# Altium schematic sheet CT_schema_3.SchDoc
size 522 x 390 mm
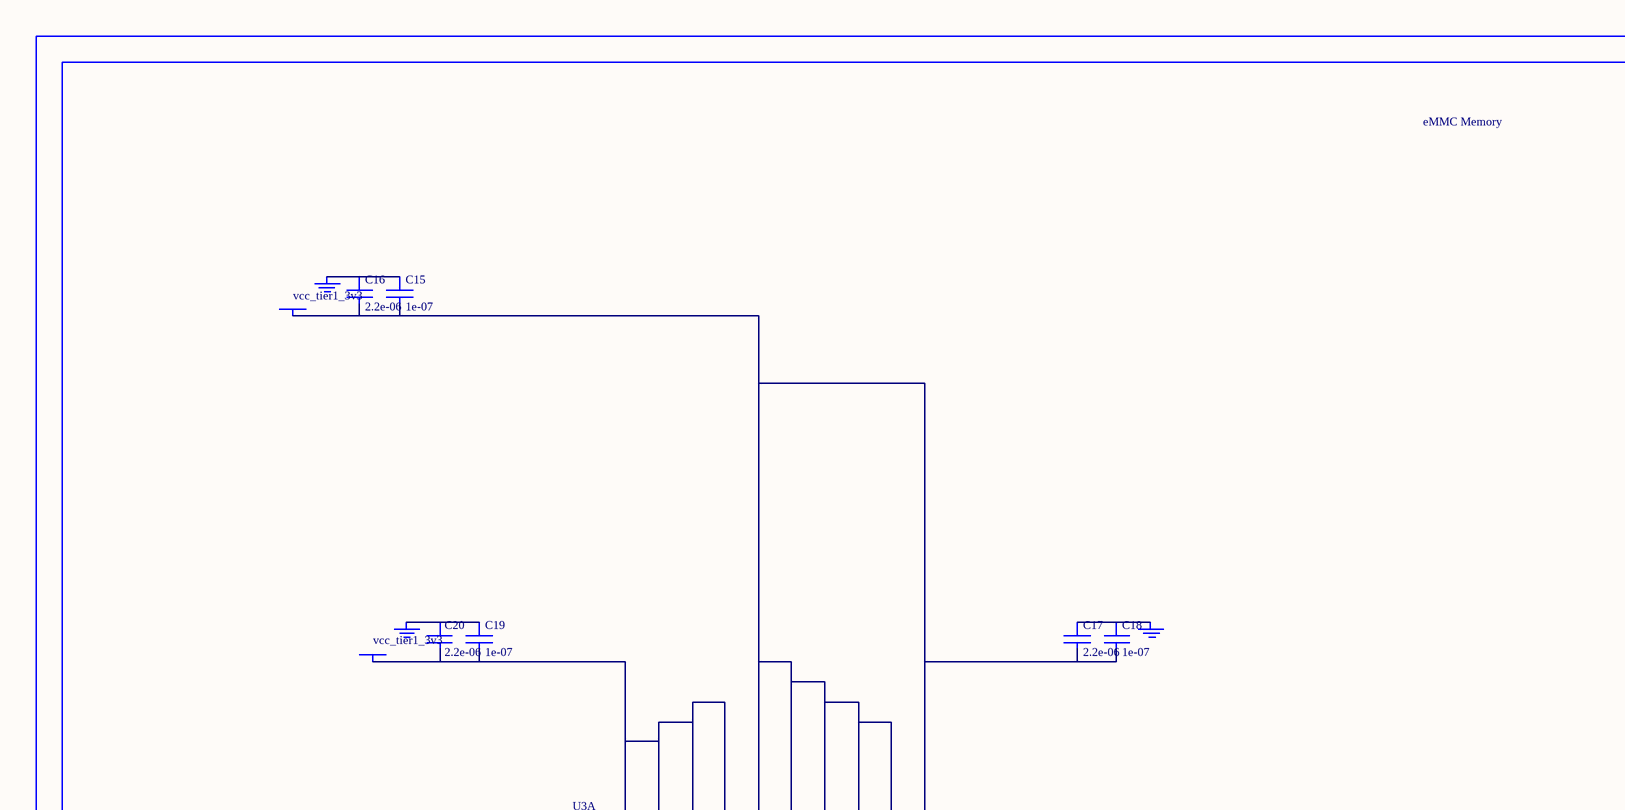
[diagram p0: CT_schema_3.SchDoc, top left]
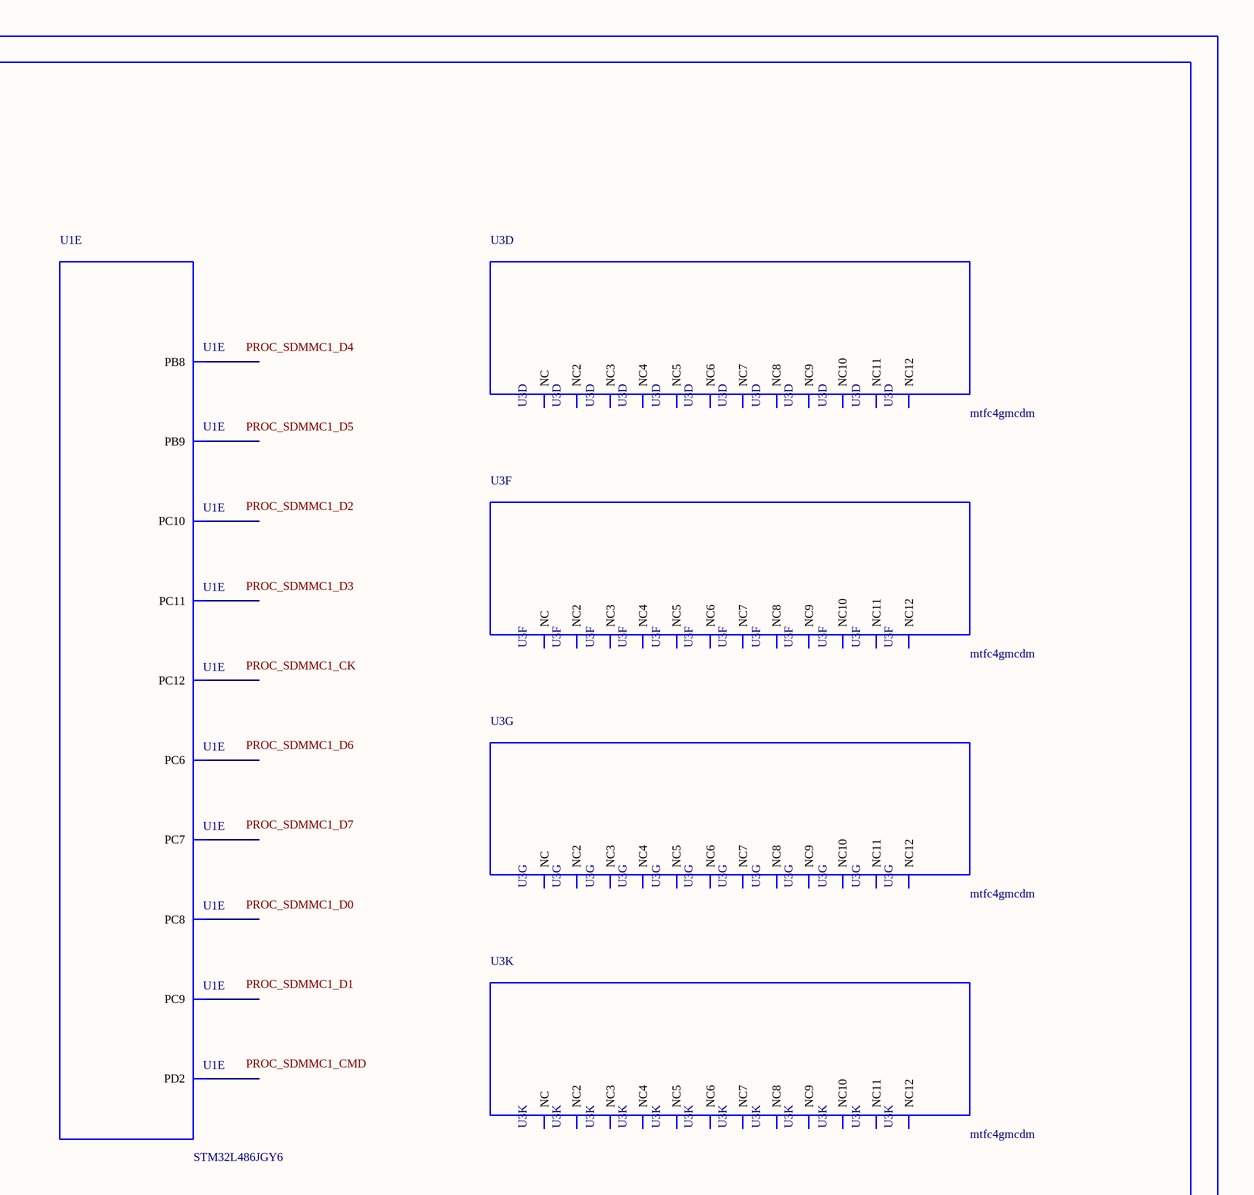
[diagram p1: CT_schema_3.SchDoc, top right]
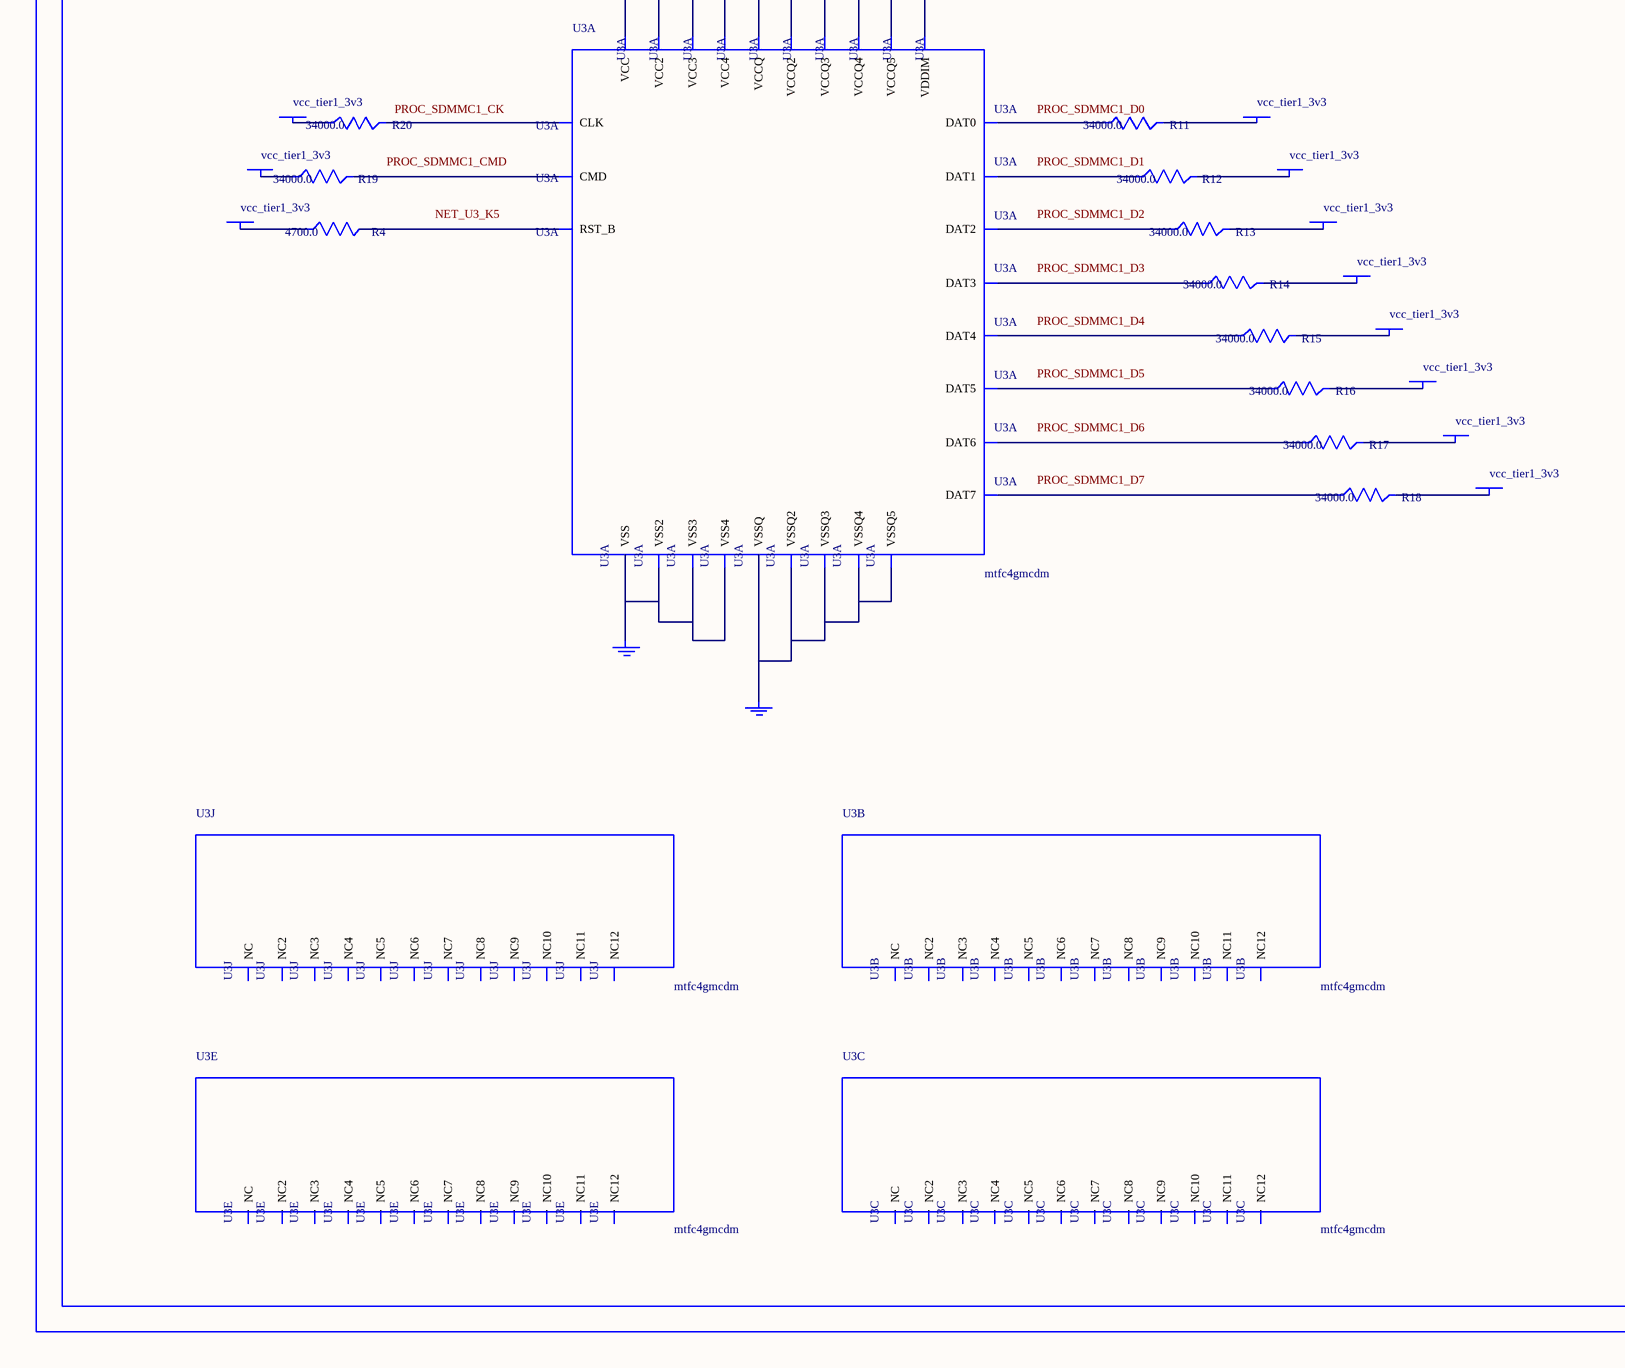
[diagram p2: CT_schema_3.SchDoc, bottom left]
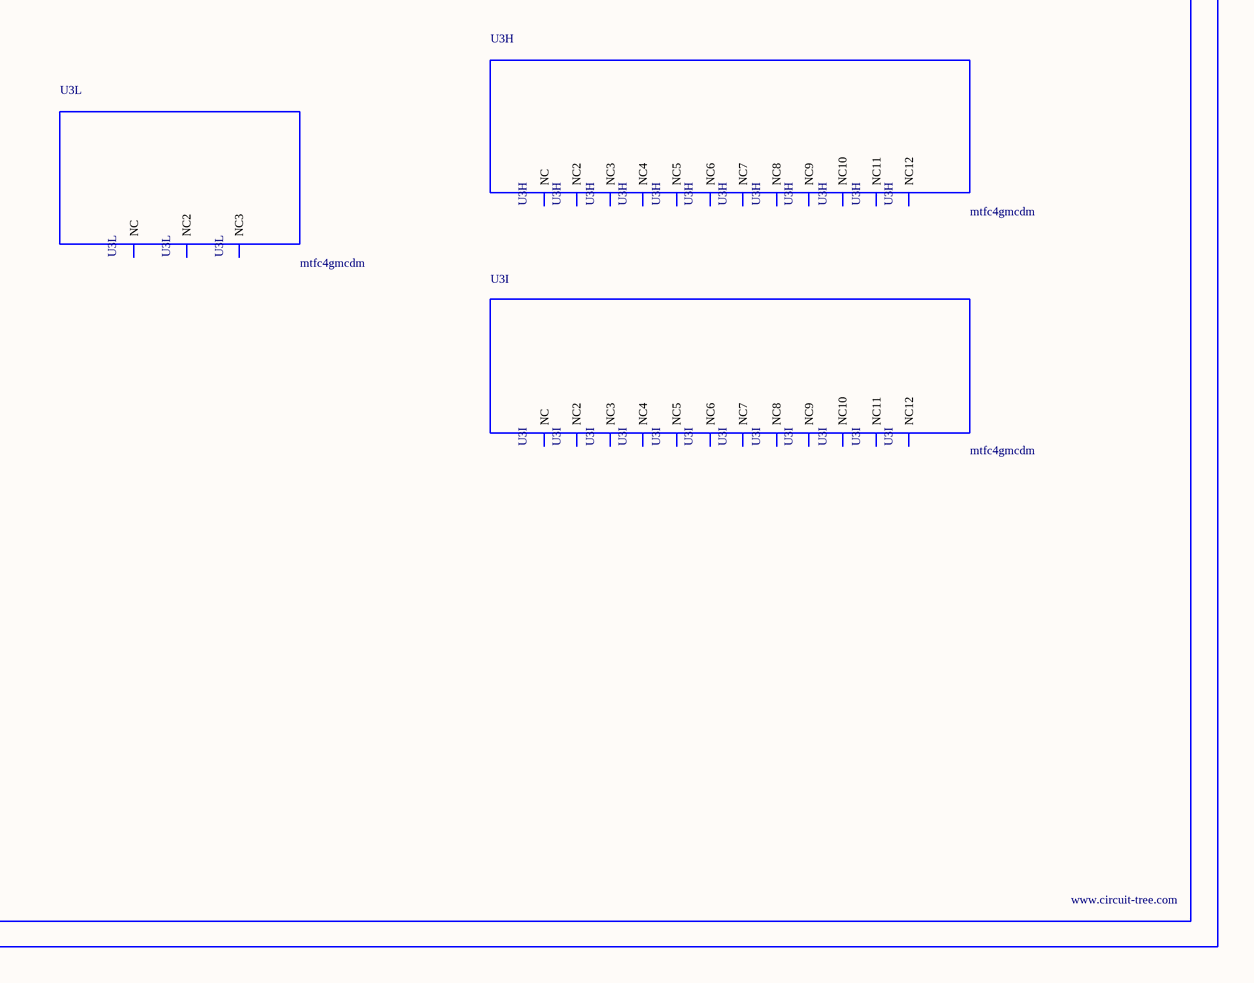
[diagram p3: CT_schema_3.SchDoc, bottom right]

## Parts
BORDER2  (no value)
C15  1e-07  [C0402]
C16  2.2e-06  [C0603]
C17  2.2e-06  [C0603]
C18  1e-07  [C0402]
C19  1e-07  [C0402]
C20  2.2e-06  [C0603]
GND_INSTANCE_2_0  (no value)
GND_INSTANCE_2_1  (no value)
GND_INSTANCE_2_2  (no value)
GND_INSTANCE_2_3  (no value)
GND_INSTANCE_2_4  (no value)
POWER_INSTANCE_2_0  vcc_tier1_3v3
POWER_INSTANCE_2_1  vcc_tier1_3v3
POWER_INSTANCE_2_2  vcc_tier1_3v3
POWER_INSTANCE_2_3  vcc_tier1_3v3
POWER_INSTANCE_2_4  vcc_tier1_3v3
POWER_INSTANCE_2_5  vcc_tier1_3v3
POWER_INSTANCE_2_6  vcc_tier1_3v3
POWER_INSTANCE_2_7  vcc_tier1_3v3
POWER_INSTANCE_2_8  vcc_tier1_3v3
POWER_INSTANCE_2_9  vcc_tier1_3v3
POWER_INSTANCE_2_10  vcc_tier1_3v3
POWER_INSTANCE_2_11  vcc_tier1_3v3
POWER_INSTANCE_2_12  vcc_tier1_3v3
R4  4700.0  [R0603]
R11  34000.0  [R0603]
R12  34000.0  [R0603]
R13  34000.0  [R0603]
R14  34000.0  [R0603]
R15  34000.0  [R0603]
R16  34000.0  [R0603]
R17  34000.0  [R0603]
R18  34000.0  [R0603]
R19  34000.0  [R0603]
R20  34000.0  [R0603]
U1  STM32L486JGY6  [WLCSP72]  (part E of 7)
U3  mtfc4gmcdm  [TFBGA-153]  (parts A,B,C,D,E,F,G,H,I,J,K,L of 12)

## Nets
NetC15_1: C15.1 C16.1 GND_INSTANCE_2_0.0(GND)
NetC15_2: C15.2 C16.2 C17.2 C18.2 POWER_INSTANCE_2_0.0(PWR) U3.C2(VDDIM) U3.C6(VCCQ) U3.M4(VCCQ2) U3.N4(VCCQ3) U3.P3(VCCQ4) U3.P5(VCCQ5)
NetC17_1: C17.1 C18.1 GND_INSTANCE_2_1.0(GND)
NetC19_1: C19.1 C20.1 GND_INSTANCE_2_2.0(GND)
NetC19_2: C19.2 C20.2 POWER_INSTANCE_2_1.0(PWR) U3.E6(VCC) U3.F5(VCC2) U3.J10(VCC3) U3.K9(VCC4)
NetGND_INSTANCE_2_3_0: GND_INSTANCE_2_3.0(GND) U3.E7(VSS) U3.G5(VSS2) U3.H10(VSS3) U3.K8(VSS4)
NetGND_INSTANCE_2_4_0: GND_INSTANCE_2_4.0(GND) U3.C4(VSSQ) U3.N2(VSSQ2) U3.N5(VSSQ3) U3.P4(VSSQ4) U3.P6(VSSQ5)
NetPOWER_INSTANCE_2_2_0: POWER_INSTANCE_2_2.0(PWR) R11.2
NetPOWER_INSTANCE_2_3_0: POWER_INSTANCE_2_3.0(PWR) R12.2
NetPOWER_INSTANCE_2_4_0: POWER_INSTANCE_2_4.0(PWR) R13.2
NetPOWER_INSTANCE_2_5_0: POWER_INSTANCE_2_5.0(PWR) R14.2
NetPOWER_INSTANCE_2_6_0: POWER_INSTANCE_2_6.0(PWR) R15.2
NetPOWER_INSTANCE_2_7_0: POWER_INSTANCE_2_7.0(PWR) R16.2
NetPOWER_INSTANCE_2_8_0: POWER_INSTANCE_2_8.0(PWR) R17.2
NetPOWER_INSTANCE_2_9_0: POWER_INSTANCE_2_9.0(PWR) R18.2
NetPOWER_INSTANCE_2_10_0: POWER_INSTANCE_2_10.0(PWR) R19.1
NetPOWER_INSTANCE_2_11_0: POWER_INSTANCE_2_11.0(PWR) R20.1
NetPOWER_INSTANCE_2_12_0: POWER_INSTANCE_2_12.0(PWR) R4.1
NetR4_2: R4.2 U3.K5(RST_B)
NetR11_1: R11.1 U3.A3(DAT0)
NetR12_1: R12.1 U3.A4(DAT1)
NetR13_1: R13.1 U3.A5(DAT2)
NetR14_1: R14.1 U3.B2(DAT3)
NetR15_1: R15.1 U3.B3(DAT4)
NetR16_1: R16.1 U3.B4(DAT5)
NetR17_1: R17.1 U3.B5(DAT6)
NetR18_1: R18.1 U3.B6(DAT7)
NetR19_2: R19.2 U3.M5(CMD)
NetR20_2: R20.2 U3.M6(CLK)

Not connected (* = marked no-connect by the designer): U1 A3(PD2) B3(PC12) C3(PC11) D3(PC10) E1(PC9) E7(PB8) E8(PB9) F1(PC7) F2(PC8) F3(PC6); U3 A1(NC) A2(NC7) A6(NC8) A7(NC9) A8(NC10) A9(NC11) A10(NC2) A11(NC3) A12(NC4) A13(NC5) A14(NC6) B1(NC12) B7(NC6) B8(NC7) B9(NC8) B10(NC) B11(NC2) B12(NC3) B13(NC4) B14(NC5) C1(NC9) C3(NC10) C5(NC11) C7(NC12) C8(NC6) C9(NC7) C10(NC) C11(NC2) C12(NC3) C13(NC4) C14(NC5) D1(NC8) D2(NC10) D3(NC11) D4(NC12) D12(NC9) D13(NC) D14(NC2) E1(NC3) E2(NC8) E3(NC9) E5(NC10) E8(NC11) E9(NC12) E10(NC4) E12(NC5) E13(NC6) E14(NC7) F1(NC) F2(NC6) F3(NC7) F10(NC2) F12(NC3) F13(NC4) F14(NC5) G1(NC8) G2(NC11) G3(NC12) G10(NC9) G12(NC10) G13(NC) G14(NC2) H1(NC3) H2(NC7) H3(NC8) H5(NC9) H12(NC4) H13(NC5) H14(NC6) J1(NC10) J2(NC11) J3(NC12) J5(NC4) J12(NC) J13(NC2) J14(NC3) K1(NC5) K2(NC9) K3(NC10) K6(NC11) K7(NC12) K10(NC6) K12(NC7) K13(NC8) K14(NC) L1(NC2) L2(NC6) L3(NC7) L12(NC3) L13(NC4) L14(NC5) M1(NC8) M2(NC9) M3(NC10) M7(NC11) M8(NC12) M9(NC6) M10(NC) M11(NC2) M12(NC3) M13(NC4) M14(NC5) N1(NC7) N3(NC8) N6(NC9) N7(NC10) N8(NC11) N9(NC12) N10(NC) N11(NC2) N12(NC3) N13(NC4) N14(NC5) P1(NC6) P2(NC9) P7(NC10) P8(NC11) P9(NC12) P10(NC7) P11(NC8) P12(NC) P13(NC2) P14(NC3)

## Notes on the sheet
- Labels drawn without touching a wire or pin: NET_U3_K5, PROC_SDMMC1_CK, PROC_SDMMC1_CMD, PROC_SDMMC1_D0, PROC_SDMMC1_D1, PROC_SDMMC1_D2, PROC_SDMMC1_D3, PROC_SDMMC1_D4, PROC_SDMMC1_D5, PROC_SDMMC1_D6, PROC_SDMMC1_D7

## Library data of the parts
BORDER2 = BORDER_PAGE2
C15 C18 C19 = C0402C104K3RACTU
C16 C17 C20 = C0603C225K8RACTU
GND_INSTANCE_2_0-GND_INSTANCE_2_4 = GND
POWER_INSTANCE_2_0-POWER_INSTANCE_2_12 = PWR
R4 = RC0603JR-074K7L
R11-R20 = ERA3ARB3402V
